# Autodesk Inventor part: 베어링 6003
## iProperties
IsCustomPart: 1
Company: 한국ATC센터
Created: 2014-07
Part Number: 베어링 6003
Material: 강, 연강
Description: 깊은 그루브 볼 베어링
Document SubType Name: Modeling
Standard: KS B 2023
Designer: KYOUNG IL JANG
Standards Organization: KS
Language: ko-KR
Size Designation: 6003 - 17 x 35 x 10
Categories: <MemberInstance><Categories><Category DisplayName="샤프트 부품" InternalName="7f7aeb1f-a693-4053-b835-cee3144e0d98" Mnemonic="SHFT"><Category DisplayName="베어링" Inter
Density: 1 g/cm^3
Author: KYOUNG IL JANG
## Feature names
1. IDS_ARRAYBALL[SIMPL:T] [Circular Pattern]
